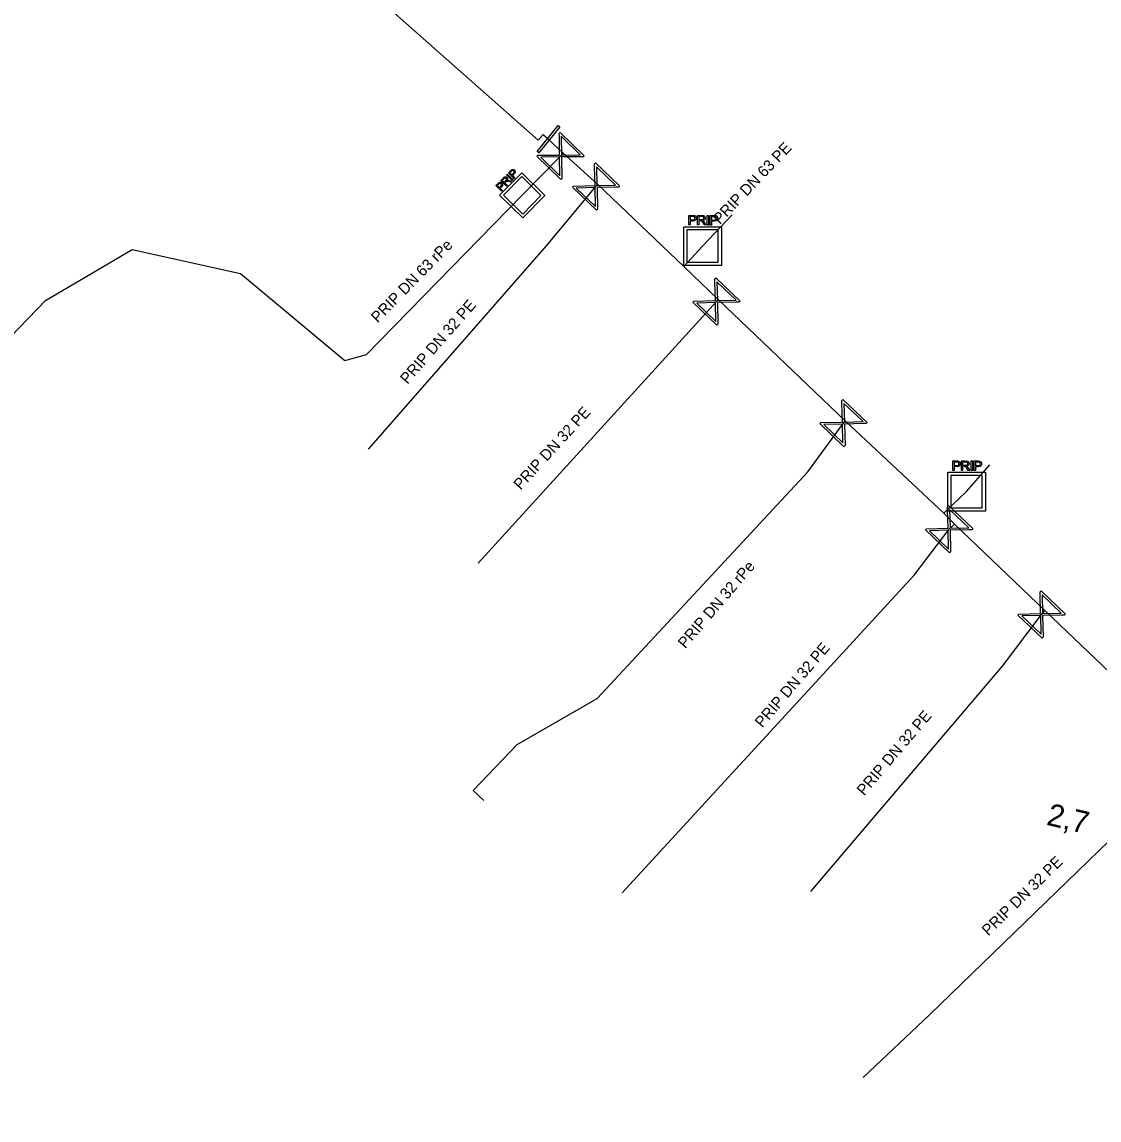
# Model space of a CAD drawing. Extents: x -643842 to -636370, y -1119190 to -1110210.
# Drawn here: x -642458.59 to -642410.27, y -1113929.96 to -1113880.7 of the extents above; entities that cross this region are included whole.
import ezdxf

# ---------------------------------------------------------------- set-up
doc = ezdxf.new("R2010")
doc.units = 0
for name, color, linetype in [('22', 7, 'Continuous'), ('Default', 7, 'Continuous'), ('Level 10', 7, 'Continuous'), ('Level 16', 7, 'Continuous'), ('Level 18', 7, 'Continuous'), ('Level 21', 7, 'Continuous'), ('Level 23', 7, 'Continuous')]:
    doc.layers.add(name, color=color, linetype=linetype)

msp = doc.modelspace()

# ---------------------------------------------------------------- linework, layer by layer
at = {"layer": 'Default'}
for points in [[(-642436.995, -1113887.698), (-642436.961, -1113887.664), (-642436.937, -1113887.653), (-642436.913, -1113887.641), (-642436.885, -1113887.648), (-642436.857, -1113887.655), (-642436.836, -1113887.675), (-642436.808, -1113887.702), (-642436.807, -1113887.738), (-642436.806, -1113887.773), (-642436.836, -1113887.815), (-642436.816, -1113887.809), (-642436.803, -1113887.808), (-642436.776, -1113887.806), (-642436.742, -1113887.813)], [(-642436.674, -1113887.371), (-642436.649, -1113887.346), (-642436.633, -1113887.334), (-642436.612, -1113887.319), (-642436.59, -1113887.315), (-642436.569, -1113887.31), (-642436.546, -1113887.318), (-642436.523, -1113887.326), (-642436.503, -1113887.345), (-642436.47, -1113887.377), (-642436.468, -1113887.419), (-642436.466, -1113887.462), (-642436.519, -1113887.516)], [(-642436.548, -1113887.487), (-642436.516, -1113887.454), (-642436.515, -1113887.428), (-642436.514, -1113887.403), (-642436.537, -1113887.381), (-642436.552, -1113887.365), (-642436.571, -1113887.362), (-642436.59, -1113887.359), (-642436.607, -1113887.368), (-642436.618, -1113887.375), (-642436.641, -1113887.398)], [(-642437.235, -1113887.944), (-642437.21, -1113887.919), (-642437.194, -1113887.907), (-642437.173, -1113887.892), (-642437.151, -1113887.888), (-642437.13, -1113887.883), (-642437.107, -1113887.891), (-642437.084, -1113887.899), (-642437.065, -1113887.918), (-642437.031, -1113887.95), (-642437.029, -1113887.992), (-642437.027, -1113888.035), (-642437.08, -1113888.089)], [(-642437.11, -1113888.06), (-642437.077, -1113888.027), (-642437.076, -1113888.001), (-642437.075, -1113887.976), (-642437.098, -1113887.954), (-642437.114, -1113887.938), (-642437.133, -1113887.935), (-642437.152, -1113887.932), (-642437.168, -1113887.941), (-642437.179, -1113887.948), (-642437.202, -1113887.971)], [(-642436.888, -1113887.816), (-642436.865, -1113887.792), (-642436.857, -1113887.774), (-642436.849, -1113887.756), (-642436.853, -1113887.74), (-642436.857, -1113887.723), (-642436.87, -1113887.71), (-642436.888, -1113887.693), (-642436.912, -1113887.695), (-642436.937, -1113887.696), (-642436.965, -1113887.725)], [(-642436.756, -1113887.861), (-642436.794, -1113887.852), (-642436.816, -1113887.85), (-642436.838, -1113887.848), (-642436.85, -1113887.851), (-642436.862, -1113887.854), (-642436.872, -1113887.86), (-642436.879, -1113887.864), (-642436.892, -1113887.877)], [(-642428.513, -1113889.374), (-642428.47, -1113889.374), (-642428.447, -1113889.378), (-642428.416, -1113889.384), (-642428.394, -1113889.399), (-642428.372, -1113889.414), (-642428.359, -1113889.44), (-642428.347, -1113889.466), (-642428.347, -1113889.498), (-642428.347, -1113889.554), (-642428.381, -1113889.592), (-642428.416, -1113889.629), (-642428.507, -1113889.629)], [(-642428.507, -1113889.579), (-642428.451, -1113889.579), (-642428.428, -1113889.559), (-642428.406, -1113889.538), (-642428.406, -1113889.5), (-642428.406, -1113889.474), (-642428.419, -1113889.455), (-642428.432, -1113889.436), (-642428.454, -1113889.43), (-642428.469, -1113889.425), (-642428.508, -1113889.425)], [(-642428.039, -1113889.715), (-642428.064, -1113889.676), (-642428.08, -1113889.655), (-642428.097, -1113889.635), (-642428.11, -1113889.627), (-642428.123, -1113889.619), (-642428.136, -1113889.616), (-642428.145, -1113889.613), (-642428.167, -1113889.613)], [(-642428.111, -1113889.564), (-642428.072, -1113889.564), (-642428.05, -1113889.556), (-642428.028, -1113889.548), (-642428.017, -1113889.531), (-642428.006, -1113889.513), (-642428.006, -1113889.491), (-642428.006, -1113889.462), (-642428.028, -1113889.442), (-642428.05, -1113889.422), (-642428.098, -1113889.422)], [(-642428.099, -1113889.374), (-642428.042, -1113889.374), (-642428.012, -1113889.386), (-642427.982, -1113889.397), (-642427.965, -1113889.427), (-642427.947, -1113889.456), (-642427.947, -1113889.491), (-642427.947, -1113889.538), (-642427.976, -1113889.569), (-642428.006, -1113889.6), (-642428.067, -1113889.608), (-642428.045, -1113889.62), (-642428.034, -1113889.63), (-642428.009, -1113889.652), (-642427.987, -1113889.687)], [(-642427.55, -1113889.375), (-642427.508, -1113889.375), (-642427.484, -1113889.38), (-642427.453, -1113889.386), (-642427.432, -1113889.4), (-642427.41, -1113889.415), (-642427.397, -1113889.441), (-642427.385, -1113889.468), (-642427.385, -1113889.5), (-642427.385, -1113889.556), (-642427.419, -1113889.593), (-642427.453, -1113889.63), (-642427.544, -1113889.63)], [(-642427.544, -1113889.581), (-642427.489, -1113889.581), (-642427.466, -1113889.56), (-642427.443, -1113889.54), (-642427.443, -1113889.501), (-642427.443, -1113889.475), (-642427.456, -1113889.456), (-642427.47, -1113889.437), (-642427.492, -1113889.431), (-642427.506, -1113889.427), (-642427.546, -1113889.427)], [(-642416.672, -1113900.391), (-642416.629, -1113900.391), (-642416.606, -1113900.395), (-642416.575, -1113900.401), (-642416.553, -1113900.416), (-642416.531, -1113900.431), (-642416.518, -1113900.457), (-642416.506, -1113900.483), (-642416.506, -1113900.515), (-642416.506, -1113900.571), (-642416.54, -1113900.609), (-642416.575, -1113900.646), (-642416.666, -1113900.646)], [(-642416.666, -1113900.596), (-642416.61, -1113900.596), (-642416.587, -1113900.576), (-642416.565, -1113900.555), (-642416.565, -1113900.517), (-642416.565, -1113900.491), (-642416.578, -1113900.472), (-642416.591, -1113900.453), (-642416.613, -1113900.447), (-642416.628, -1113900.442), (-642416.667, -1113900.442)], [(-642416.27, -1113900.581), (-642416.231, -1113900.581), (-642416.209, -1113900.573), (-642416.187, -1113900.565), (-642416.176, -1113900.548), (-642416.165, -1113900.53), (-642416.165, -1113900.508), (-642416.165, -1113900.479), (-642416.187, -1113900.459), (-642416.209, -1113900.439), (-642416.257, -1113900.439)], [(-642416.258, -1113900.391), (-642416.201, -1113900.391), (-642416.171, -1113900.403), (-642416.141, -1113900.414), (-642416.124, -1113900.444), (-642416.106, -1113900.473), (-642416.106, -1113900.508), (-642416.106, -1113900.555), (-642416.135, -1113900.586), (-642416.165, -1113900.617), (-642416.226, -1113900.625), (-642416.204, -1113900.637), (-642416.193, -1113900.647), (-642416.168, -1113900.669), (-642416.146, -1113900.704)], [(-642415.709, -1113900.392), (-642415.667, -1113900.392), (-642415.643, -1113900.397), (-642415.612, -1113900.403), (-642415.591, -1113900.417), (-642415.569, -1113900.432), (-642415.556, -1113900.458), (-642415.544, -1113900.485), (-642415.544, -1113900.517), (-642415.544, -1113900.573), (-642415.578, -1113900.61), (-642415.612, -1113900.647), (-642415.703, -1113900.647)], [(-642415.703, -1113900.598), (-642415.648, -1113900.598), (-642415.625, -1113900.577), (-642415.602, -1113900.557), (-642415.602, -1113900.518), (-642415.602, -1113900.492), (-642415.615, -1113900.473), (-642415.629, -1113900.454), (-642415.651, -1113900.448), (-642415.665, -1113900.444), (-642415.705, -1113900.444)], [(-642416.198, -1113900.732), (-642416.223, -1113900.693), (-642416.239, -1113900.672), (-642416.256, -1113900.652), (-642416.269, -1113900.644), (-642416.282, -1113900.636), (-642416.295, -1113900.633), (-642416.304, -1113900.63), (-642416.326, -1113900.63)]]:
    msp.add_open_spline(points, degree=3, dxfattribs=at)
at = {"layer": 'Level 16'}
for points in [[(-642434.443, -1113885.649), (-642433.37, -1113886.697), (-642433.416, -1113886.744), (-642433.544, -1113886.742), (-642434.384, -1113886.753), (-642434.372, -1113887.723), (-642434.418, -1113887.77), (-642435.491, -1113886.722), (-642435.445, -1113886.675), (-642434.473, -1113886.666), (-642434.484, -1113885.826), (-642434.489, -1113885.696), (-642434.443, -1113885.649)], [(-642434.462, -1113885.406), (-642435.406, -1113886.572), (-642435.478, -1113886.513), (-642434.535, -1113885.347), (-642434.462, -1113885.406)], [(-642434.396, -1113885.826), (-642434.385, -1113886.665), (-642433.548, -1113886.654), (-642434.396, -1113885.826)], [(-642434.461, -1113887.597), (-642434.472, -1113886.754), (-642435.313, -1113886.765), (-642434.461, -1113887.597)], [(-642432.866, -1113887.02), (-642431.78, -1113888.055), (-642431.826, -1113888.103), (-642431.954, -1113888.102), (-642432.794, -1113888.123), (-642432.77, -1113889.093), (-642432.815, -1113889.141), (-642433.901, -1113888.106), (-642433.855, -1113888.058), (-642432.884, -1113888.037), (-642432.905, -1113887.197), (-642432.911, -1113887.068), (-642432.866, -1113887.02)], [(-642432.816, -1113887.196), (-642432.796, -1113888.035), (-642431.959, -1113888.014), (-642432.816, -1113887.196)], [(-642432.861, -1113888.968), (-642432.882, -1113888.125), (-642433.723, -1113888.146), (-642432.861, -1113888.968)], [(-642427.466, -1113892.18), (-642426.38, -1113893.215), (-642426.426, -1113893.263), (-642426.554, -1113893.262), (-642427.394, -1113893.283), (-642427.37, -1113894.253), (-642427.415, -1113894.301), (-642428.501, -1113893.266), (-642428.455, -1113893.218), (-642427.484, -1113893.197), (-642427.505, -1113892.357), (-642427.511, -1113892.228), (-642427.466, -1113892.18)], [(-642427.416, -1113892.356), (-642427.396, -1113893.195), (-642426.559, -1113893.174), (-642427.416, -1113892.356)], [(-642427.461, -1113894.128), (-642427.482, -1113893.285), (-642428.323, -1113893.306), (-642427.461, -1113894.128)], [(-642421.766, -1113897.63), (-642420.68, -1113898.665), (-642420.726, -1113898.713), (-642420.854, -1113898.712), (-642421.694, -1113898.733), (-642421.67, -1113899.703), (-642421.715, -1113899.751), (-642422.801, -1113898.716), (-642422.755, -1113898.668), (-642421.784, -1113898.647), (-642421.805, -1113897.807), (-642421.811, -1113897.678), (-642421.766, -1113897.63)], [(-642421.716, -1113897.806), (-642421.696, -1113898.645), (-642420.859, -1113898.624), (-642421.716, -1113897.806)], [(-642421.761, -1113899.578), (-642421.782, -1113898.735), (-642422.623, -1113898.756), (-642421.761, -1113899.578)], [(-642417.027, -1113902.393), (-642415.941, -1113903.428), (-642415.987, -1113903.476), (-642416.115, -1113903.475), (-642416.955, -1113903.496), (-642416.931, -1113904.466), (-642416.976, -1113904.514), (-642418.062, -1113903.479), (-642418.016, -1113903.431), (-642417.045, -1113903.41), (-642417.066, -1113902.57), (-642417.072, -1113902.441), (-642417.027, -1113902.393)], [(-642416.977, -1113902.569), (-642416.957, -1113903.408), (-642416.12, -1113903.387), (-642416.977, -1113902.569)], [(-642417.022, -1113904.341), (-642417.043, -1113903.498), (-642417.884, -1113903.519), (-642417.022, -1113904.341)], [(-642412.876, -1113906.22), (-642411.79, -1113907.255), (-642411.836, -1113907.303), (-642411.964, -1113907.302), (-642412.804, -1113907.323), (-642412.78, -1113908.293), (-642412.825, -1113908.341), (-642413.911, -1113907.306), (-642413.865, -1113907.258), (-642412.894, -1113907.237), (-642412.915, -1113906.397), (-642412.921, -1113906.268), (-642412.876, -1113906.22)], [(-642412.826, -1113906.396), (-642412.806, -1113907.235), (-642411.969, -1113907.214), (-642412.826, -1113906.396)], [(-642412.871, -1113908.168), (-642412.892, -1113907.325), (-642413.733, -1113907.346), (-642412.871, -1113908.168)]]:
    msp.add_lwpolyline(points, dxfattribs=at)
at = {"layer": 'Level 18'}
for points in [[(-642436.174, -1113887.462), (-642435.136, -1113888.476), (-642436.123, -1113889.487), (-642437.162, -1113888.473), (-642436.174, -1113887.462)], [(-642436.989, -1113888.473), (-642436.127, -1113889.314), (-642435.308, -1113888.476), (-642436.17, -1113887.634), (-642436.989, -1113888.473)], [(-642436.594, -1113887.803), (-642436.851, -1113887.552), (-642436.818, -1113887.519), (-642436.561, -1113887.769), (-642436.594, -1113887.803)], [(-642436.511, -1113887.718), (-642436.768, -1113887.467), (-642436.674, -1113887.371)], [(-642436.641, -1113887.398), (-642436.705, -1113887.464), (-642436.613, -1113887.553)], [(-642436.613, -1113887.553), (-642436.548, -1113887.487)], [(-642436.519, -1113887.516), (-642436.583, -1113887.582), (-642436.479, -1113887.685), (-642436.511, -1113887.718)], [(-642437.072, -1113888.291), (-642437.329, -1113888.04), (-642437.235, -1113887.944)], [(-642437.202, -1113887.971), (-642437.266, -1113888.037), (-642437.174, -1113888.126)], [(-642437.174, -1113888.126), (-642437.11, -1113888.06)], [(-642437.08, -1113888.089), (-642437.145, -1113888.155), (-642437.04, -1113888.258), (-642437.072, -1113888.291)], [(-642436.849, -1113888.062), (-642437.106, -1113887.811), (-642436.995, -1113887.698)], [(-642436.965, -1113887.725), (-642437.043, -1113887.805), (-642436.959, -1113887.888)], [(-642436.959, -1113887.888), (-642436.888, -1113887.816)], [(-642436.892, -1113887.877), (-642436.93, -1113887.916), (-642436.816, -1113888.028), (-642436.849, -1113888.062)], [(-642436.742, -1113887.813), (-642436.629, -1113887.837), (-642436.671, -1113887.879), (-642436.756, -1113887.861)], [(-642428.674, -1113889.805), (-642428.674, -1113889.374), (-642428.513, -1113889.374)], [(-642428.507, -1113889.629), (-642428.618, -1113889.629), (-642428.618, -1113889.805), (-642428.674, -1113889.805)], [(-642428.508, -1113889.425), (-642428.618, -1113889.425), (-642428.618, -1113889.579)], [(-642428.618, -1113889.579), (-642428.507, -1113889.579)], [(-642428.29, -1113889.805), (-642428.29, -1113889.374), (-642428.099, -1113889.374)], [(-642428.167, -1113889.613), (-642428.233, -1113889.613), (-642428.233, -1113889.805), (-642428.29, -1113889.805)], [(-642428.098, -1113889.422), (-642428.233, -1113889.422), (-642428.233, -1113889.564)], [(-642428.233, -1113889.564), (-642428.111, -1113889.564)], [(-642427.853, -1113889.806), (-642427.853, -1113889.375), (-642427.798, -1113889.375), (-642427.798, -1113889.806), (-642427.853, -1113889.806)], [(-642427.711, -1113889.806), (-642427.711, -1113889.375), (-642427.55, -1113889.375)], [(-642427.544, -1113889.63), (-642427.656, -1113889.63), (-642427.656, -1113889.806), (-642427.711, -1113889.806)], [(-642427.546, -1113889.427), (-642427.656, -1113889.427), (-642427.656, -1113889.581)], [(-642427.656, -1113889.581), (-642427.544, -1113889.581)], [(-642427.209, -1113889.881), (-642427.209, -1113891.623), (-642428.905, -1113891.623), (-642428.905, -1113889.881), (-642427.209, -1113889.881)], [(-642428.76, -1113890.029), (-642428.76, -1113891.475), (-642427.354, -1113891.475), (-642427.354, -1113890.029), (-642428.76, -1113890.029)], [(-642427.987, -1113889.687), (-642427.912, -1113889.805), (-642427.984, -1113889.805), (-642428.039, -1113889.715)], [(-642416.833, -1113900.822), (-642416.833, -1113900.391), (-642416.672, -1113900.391)], [(-642416.667, -1113900.442), (-642416.777, -1113900.442), (-642416.777, -1113900.596)], [(-642416.449, -1113900.822), (-642416.449, -1113900.391), (-642416.258, -1113900.391)], [(-642416.257, -1113900.439), (-642416.392, -1113900.439), (-642416.392, -1113900.581)], [(-642416.012, -1113900.823), (-642416.012, -1113900.392), (-642415.957, -1113900.392), (-642415.957, -1113900.823), (-642416.012, -1113900.823)], [(-642415.87, -1113900.823), (-642415.87, -1113900.392), (-642415.709, -1113900.392)], [(-642415.705, -1113900.444), (-642415.815, -1113900.444), (-642415.815, -1113900.598)], [(-642415.368, -1113900.898), (-642415.368, -1113902.64), (-642417.064, -1113902.64), (-642417.064, -1113900.898), (-642415.368, -1113900.898)], [(-642416.666, -1113900.646), (-642416.777, -1113900.646), (-642416.777, -1113900.822), (-642416.833, -1113900.822)], [(-642416.777, -1113900.596), (-642416.666, -1113900.596)], [(-642416.326, -1113900.63), (-642416.392, -1113900.63), (-642416.392, -1113900.822), (-642416.449, -1113900.822)], [(-642416.392, -1113900.581), (-642416.27, -1113900.581)], [(-642416.146, -1113900.704), (-642416.071, -1113900.822), (-642416.143, -1113900.822), (-642416.198, -1113900.732)], [(-642415.703, -1113900.647), (-642415.815, -1113900.647), (-642415.815, -1113900.823), (-642415.87, -1113900.823)], [(-642415.815, -1113900.598), (-642415.703, -1113900.598)], [(-642416.919, -1113901.046), (-642416.919, -1113902.492), (-642415.513, -1113902.492), (-642415.513, -1113901.046), (-642416.919, -1113901.046)]]:
    msp.add_lwpolyline(points, dxfattribs=at)
at = {"layer": 'Level 21'}
for points in [[(-642454.52, -1113868.74), (-642454.63, -1113869.01), (-642454.529, -1113869.099), (-642435.44, -1113886), (-642435.209, -1113885.738), (-642434.97, -1113885.96)], [(-642434.757, -1113886.158), (-642434.97, -1113885.96)], [(-642434.757, -1113886.158), (-642434.32, -1113886.59), (-642432.757, -1113887.981), (-642428.894, -1113891.665), (-642427.355, -1113893.147), (-642421.665, -1113898.587), (-642417.242, -1113902.729), (-642416.765, -1113903.23), (-642412.711, -1113907.096), (-642409.435, -1113910.22), (-642406.138, -1113913.346), (-642404.352, -1113915.036), (-642391.898, -1113926.897), (-642385.4, -1113933.009), (-642382.19, -1113936.174), (-642381.1, -1113937.25), (-642380.97, -1113937.68), (-642381.95, -1113946.17), (-642382.8, -1113955.3), (-642382.85, -1113955.65)]]:
    msp.add_lwpolyline(points, dxfattribs=at)
at = {"layer": 'Level 23'}
for points in [[(-642494.94, -1113951.37), (-642498.13, -1113950.92), (-642499.05, -1113949.58), (-642497.33, -1113934.73), (-642476.94, -1113913.33), (-642457.54, -1113893.19), (-642453.65, -1113890.9), (-642448.78, -1113891.98), (-642444.1, -1113895.89), (-642443.13, -1113895.62), (-642436.151, -1113888.472), (-642434.43, -1113886.71), (-642434.316, -1113886.594)], [(-642443.047, -1113899.863), (-642435.06, -1113890.74), (-642432.84, -1113888.08), (-642432.757, -1113887.981)], [(-642428.894, -1113891.665), (-642428.057, -1113890.748), (-642426.731, -1113889.348)], [(-642438.12, -1113904.97), (-642427.44, -1113893.24), (-642427.355, -1113893.147)], [(-642437.874, -1113915.62), (-642438.344, -1113915.171), (-642436.369, -1113913.105), (-642432.79, -1113911.05), (-642428.065, -1113905.965), (-642423.34, -1113900.88), (-642421.665, -1113898.587)], [(-642432.79, -1113911.05), (-642423.34, -1113900.88), (-642421.74, -1113898.69), (-642421.665, -1113898.587)], [(-642417.242, -1113902.729), (-642416.216, -1113901.765), (-642415.18, -1113900.565)], [(-642431.661, -1113919.772), (-642418.56, -1113905.52), (-642417.001, -1113903.453), (-642416.765, -1113903.23)], [(-642423.21, -1113919.71), (-642414.6, -1113909.6), (-642412.85, -1113907.28), (-642412.711, -1113907.096)], [(-642420.861, -1113928.046), (-642417.88, -1113925.24), (-642407.92, -1113915.59), (-642406.21, -1113913.42), (-642406.138, -1113913.346)]]:
    msp.add_lwpolyline(points, dxfattribs=at)

# ---------------------------------------------------------------- texts
at = {"layer": '22'}
for s, rotation, p in [('PRIP DN 63 PE', 46.555, (-642427.278, -1113889.808)), ('PRIP DN 63 rPe', 45.6832, (-642442.631, -1113894.228)), ('PRIP DN 32 PE', 48.7985, (-642441.299, -1113896.978)), ('PRIP DN 32 PE', 47.6817, (-642436.222, -1113901.725)), ('PRIP DN 32 rPe', 49.5332, (-642428.834, -1113908.839)), ('PRIP DN 32 PE', 49.5332, (-642425.382, -1113912.391)), ('PRIP DN 32 PE', 49.5812, (-642420.811, -1113915.44)), ('PRIP DN 32 PE', 44.3833, (-642415.238, -1113921.725))]:
    msp.add_text(s, height=0.5, rotation=rotation, dxfattribs=at).set_placement(p)
at = {"layer": 'Level 10'}
msp.add_text('2,7', height=1, rotation=346.7612, dxfattribs=at).set_placement((-642412.671, -1113916.707))

doc.saveas('drawing.dxf')
